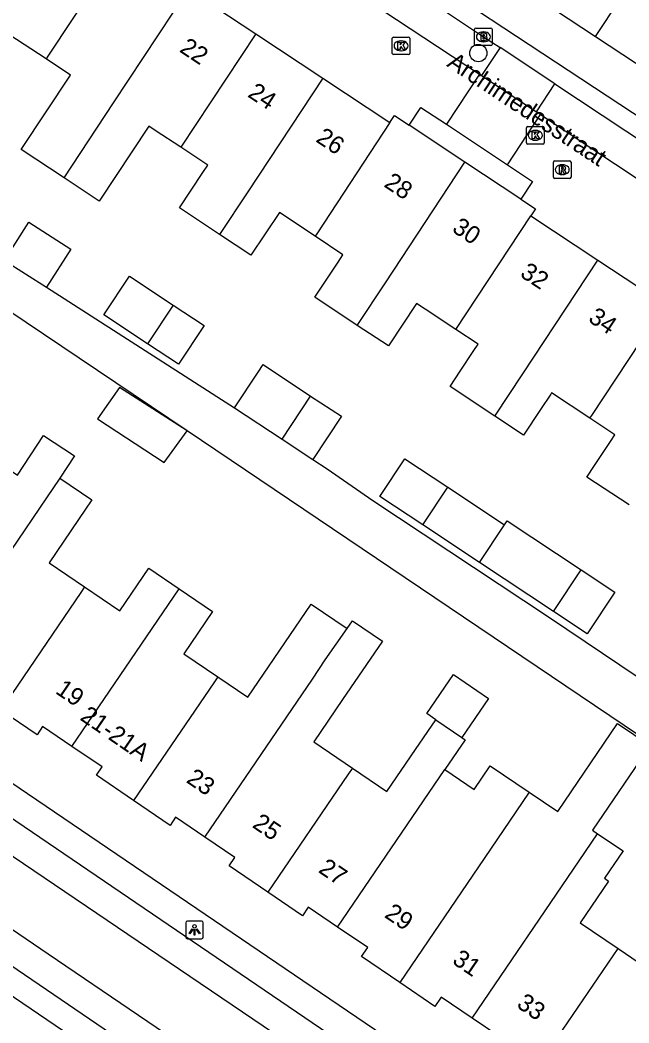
# Model space of a CAD drawing. Extents: x 159280 to 160375, y 384531 to 385872.
# Drawn here: x 159894.5 to 159929.1, y 384790.9 to 384847.8 of the extents above; entities that cross this region are included whole.
import ezdxf

# ---------------------------------------------------------------- set-up
doc = ezdxf.new("R2010")
doc.units = 0
for name, color, linetype in [('IMGEO_Boom', 7, 'Continuous'), ('IMGEO_Brandkraan', 7, 'Continuous'), ('IMGEO_Kolk', 7, 'Continuous'), ('IMGEO_Lichtpunt', 7, 'Continuous'), ('IMGEO_Openbare_ruimte_label', 7, 'Continuous'), ('IMGEO_Pand', 7, 'Continuous'), ('IMGEO_Pand_nummerreeks', 7, 'Continuous'), ('IMGEO_Rijbaan_lokaal_open', 7, 'Continuous'), ('IMGEO_Rioolput', 7, 'Continuous'), ('IMGEO_Voetpad_open', 7, 'Continuous')]:
    doc.layers.add(name, color=color, linetype=linetype)

msp = doc.modelspace()

# ---------------------------------------------------------------- linework, layer by layer
at = {"layer": 'IMGEO_Boom'}
msp.add_circle((159920.528, 384845.947), 0.489, dxfattribs=at)
at = {"layer": 'IMGEO_Brandkraan'}
for p, q in [((159920.315, 384846.443), (159920.315, 384847.295)), ((159920.39, 384847.369), (159921.242, 384847.369)), ((159920.803, 384847.149), (159920.828, 384847.149)), ((159921.316, 384847.295), (159921.316, 384846.443)), ((159920.826, 384846.589), (159920.801, 384846.589)), ((159921.242, 384846.369), (159920.39, 384846.369))]:
    msp.add_line(p, q, dxfattribs=at)
for points in [[(159920.315, 384846.443), (159920.315, 384847.295)], [(159920.39, 384847.369), (159921.242, 384847.369)], [(159920.663, 384847.069), (159920.663, 384846.669), (159920.876, 384846.669)], [(159920.894, 384847.069), (159920.663, 384847.069)], [(159920.842, 384846.988), (159920.788, 384846.988), (159920.788, 384846.912)], [(159921.316, 384847.295), (159921.316, 384846.443)], [(159920.788, 384846.912), (159920.841, 384846.912)], [(159920.85, 384846.836), (159920.788, 384846.836), (159920.788, 384846.755)], [(159920.788, 384846.755), (159920.85, 384846.755)], [(159921.242, 384846.369), (159920.39, 384846.369)]]:
    msp.add_lwpolyline(points, dxfattribs=at)
for centre, radius, start, end in [((159920.392, 384847.293), 0.0765, 91.552, 178.448), ((159920.392, 384847.293), 0.0765, 91.552, 178.448), ((159920.843, 384846.95), 0.0379, 267.8285, 90.9355), ((159920.898, 384846.924), 0.145, 59.4692, 91.5367), ((159920.923, 384846.971), 0.0922, 285.5137, 58.1501), ((159921.24, 384847.293), 0.0765, 1.552, 88.448), ((159921.24, 384847.293), 0.0765, 1.552, 88.448), ((159920.392, 384846.445), 0.0765, 181.552, 268.448), ((159920.392, 384846.445), 0.0765, 181.552, 268.448), ((159920.851, 384846.795), 0.0404, 269.8759, 90.5077), ((159920.882, 384846.92), 0.251, 268.6676, 293.5347), ((159920.928, 384846.779), 0.105, 301.3115, 78.989), ((159921.24, 384846.445), 0.0765, 271.552, 358.448), ((159921.24, 384846.445), 0.0765, 271.552, 358.448)]:
    msp.add_arc(centre, radius, start, end, dxfattribs=at)
for centre, major_axis, ratio, start_param, end_param in [((159920.802, 384846.869), (-0.387, 0.002), 0.722429, 4.712389, 7.853982), ((159920.827, 384846.869), (-0.39, 0.002), 0.717154, 1.570796, 4.712389)]:
    msp.add_ellipse(centre, major_axis=major_axis, ratio=ratio, start_param=start_param, end_param=end_param, dxfattribs=at)
at = {"layer": 'IMGEO_Kolk'}
for p, q in [((159915.647, 384845.933), (159915.647, 384846.785)), ((159915.722, 384846.859), (159916.574, 384846.859)), ((159916.135, 384846.639), (159916.16, 384846.639)), ((159916.648, 384846.785), (159916.648, 384845.933)), ((159916.574, 384845.859), (159915.722, 384845.859)), ((159916.158, 384846.079), (159916.133, 384846.079)), ((159923.261, 384840.854), (159923.261, 384841.706)), ((159923.336, 384841.78), (159924.188, 384841.78)), ((159923.749, 384841.56), (159923.774, 384841.56)), ((159924.262, 384841.706), (159924.262, 384840.854)), ((159924.188, 384840.78), (159923.336, 384840.78)), ((159923.772, 384841), (159923.747, 384841))]:
    msp.add_line(p, q, dxfattribs=at)
for points in [[(159915.647, 384845.933), (159915.647, 384846.785)], [(159915.722, 384846.859), (159916.574, 384846.859)], [(159915.968, 384846.559), (159916.091, 384846.559), (159916.091, 384846.408), (159916.221, 384846.559), (159916.385, 384846.559), (159916.239, 384846.408), (159916.392, 384846.159), (159916.24, 384846.159), (159916.155, 384846.323), (159916.091, 384846.256), (159916.091, 384846.159), (159915.968, 384846.159), (159915.968, 384846.559)], [(159916.648, 384846.785), (159916.648, 384845.933)], [(159916.574, 384845.859), (159915.722, 384845.859)], [(159923.261, 384840.854), (159923.261, 384841.706)], [(159923.336, 384841.78), (159924.188, 384841.78)], [(159923.582, 384841.48), (159923.705, 384841.48), (159923.705, 384841.329), (159923.835, 384841.48), (159923.999, 384841.48), (159923.853, 384841.329), (159924.006, 384841.08), (159923.854, 384841.08), (159923.769, 384841.244), (159923.705, 384841.177), (159923.705, 384841.08), (159923.582, 384841.08), (159923.582, 384841.48)], [(159924.262, 384841.706), (159924.262, 384840.854)], [(159924.188, 384840.78), (159923.336, 384840.78)]]:
    msp.add_lwpolyline(points, dxfattribs=at)
for centre, start, end in [((159915.724, 384846.783), 91.552, 178.448), ((159915.724, 384846.783), 91.552, 178.448), ((159916.572, 384846.783), 1.552, 88.448), ((159916.572, 384846.783), 1.552, 88.448), ((159915.724, 384845.935), 181.552, 268.448), ((159915.724, 384845.935), 181.552, 268.448), ((159916.572, 384845.935), 271.552, 358.448), ((159916.572, 384845.935), 271.552, 358.448), ((159923.338, 384841.704), 91.552, 178.448), ((159923.338, 384841.704), 91.552, 178.448), ((159924.186, 384841.704), 1.552, 88.448), ((159924.186, 384841.704), 1.552, 88.448), ((159923.338, 384840.856), 181.552, 268.448), ((159923.338, 384840.856), 181.552, 268.448), ((159924.186, 384840.856), 271.552, 358.448), ((159924.186, 384840.856), 271.552, 358.448)]:
    msp.add_arc(centre, 0.0765, start, end, dxfattribs=at)
for centre, major_axis, ratio, start_param, end_param in [((159916.134, 384846.359), (-0.387, 0.002), 0.722429, 4.712389, 7.853982), ((159916.159, 384846.359), (-0.39, 0.002), 0.717154, 1.570796, 4.712389), ((159923.748, 384841.28), (-0.387, 0.002), 0.722429, 4.712389, 7.853982), ((159923.773, 384841.28), (-0.39, 0.002), 0.717154, 1.570796, 4.712389)]:
    msp.add_ellipse(centre, major_axis=major_axis, ratio=ratio, start_param=start_param, end_param=end_param, dxfattribs=at)
at = {"layer": 'IMGEO_Lichtpunt'}
for p, q in [((159903.929, 384796.604), (159903.929, 384795.797)), ((159903.929, 384796.604), (159903.929, 384795.797)), ((159904.831, 384796.699), (159904.023, 384796.699)), ((159904.831, 384796.699), (159904.023, 384796.699)), ((159904.925, 384795.797), (159904.925, 384796.604)), ((159904.925, 384795.797), (159904.925, 384796.604)), ((159904.023, 384795.703), (159904.831, 384795.703)), ((159904.023, 384795.703), (159904.831, 384795.703))]:
    msp.add_line(p, q, dxfattribs=at)
for points in [[(159904.303, 384796.268), (159904.342, 384796.24), (159904.154, 384795.978), (159904.116, 384796.005), (159904.303, 384796.268)], [(159904.405, 384796.22), (159904.452, 384796.22), (159904.452, 384795.898), (159904.405, 384795.898), (159904.405, 384796.22)], [(159904.515, 384796.24), (159904.553, 384796.267), (159904.74, 384796.005), (159904.701, 384795.977), (159904.515, 384796.24)]]:
    msp.add_lwpolyline(points, dxfattribs=at)
msp.add_circle((159904.428, 384796.402), 0.0994, dxfattribs=at)
for centre, start, end in [((159904.023, 384796.604), 90, 180), ((159904.023, 384796.604), 90, 180), ((159904.831, 384796.604), 0, 90), ((159904.831, 384796.604), 0, 90), ((159904.023, 384795.797), 180, 270), ((159904.023, 384795.797), 180, 270), ((159904.831, 384795.797), 270, 0), ((159904.831, 384795.797), 270, 360)]:
    msp.add_arc(centre, 0.0946, start, end, dxfattribs=at)
at = {"layer": 'IMGEO_Pand'}
for points in [[(159927.177, 384846.897), (159929.93, 384851.064), (159932.923, 384855.595)], [(159900.283, 384852.086), (159896.11, 384845.763), (159896.007, 384845.613)], [(159922.587, 384849.929), (159927.177, 384846.897)], [(159897.031, 384838.868), (159899.84, 384843.124), (159904.091, 384849.565)], [(159904.091, 384849.565), (159907.899, 384847.043)], [(159896.007, 384845.613), (159893.903, 384847.006), (159892.349, 384844.66), (159890.652, 384845.784)], [(159907.899, 384847.043), (159903.648, 384840.603)], [(159907.899, 384847.043), (159911.707, 384844.521)], [(159927.177, 384846.897), (159931.767, 384843.864)], [(159897.031, 384838.868), (159894.593, 384840.482), (159897.395, 384844.694), (159896.007, 384845.613)], [(159911.707, 384844.521), (159907.459, 384838.085), (159905.851, 384835.649)], [(159911.707, 384844.521), (159915.513, 384842.001)], [(159915.513, 384842.001), (159911.357, 384835.7), (159911.263, 384835.56)], [(159915.513, 384842.001), (159915.777, 384842.399), (159916.595, 384841.858)], [(159903.648, 384840.603), (159902.203, 384841.56), (159901.842, 384841.799), (159899.026, 384837.547), (159897.031, 384838.868)], [(159919.769, 384839.756), (159916.595, 384841.858)], [(159905.851, 384835.649), (159903.573, 384837.162), (159904.899, 384839.167), (159905.182, 384839.592), (159903.648, 384840.603)], [(159913.658, 384830.497), (159915.255, 384832.916), (159919.769, 384839.756)], [(159922.937, 384837.658), (159919.769, 384839.756)], [(159922.937, 384837.658), (159923.762, 384837.112), (159923.497, 384836.712)], [(159911.263, 384835.56), (159909.243, 384836.898), (159907.624, 384834.475), (159905.851, 384835.649)], [(159893.651, 384834.187), (159895.036, 384836.353), (159897.421, 384834.828), (159896.036, 384832.662)], [(159919.246, 384830.273), (159923.497, 384836.712)], [(159923.497, 384836.712), (159927.31, 384834.199)], [(159913.658, 384830.497), (159911.258, 384832.104), (159912.575, 384834.093), (159912.85, 384834.509), (159911.263, 384835.56)], [(159893.651, 384834.187), (159896.036, 384832.662)], [(159921.465, 384825.342), (159923.055, 384827.751), (159927.31, 384834.199)], [(159927.31, 384834.199), (159931.124, 384831.685)], [(159901.764, 384829.455), (159899.286, 384831.091), (159900.733, 384833.283), (159903.211, 384831.647)], [(159903.211, 384831.647), (159904.972, 384830.484), (159903.526, 384828.293), (159901.764, 384829.455)], [(159903.211, 384831.647), (159901.764, 384829.455)], [(159919.246, 384830.273), (159917.508, 384831.424), (159917.021, 384831.747), (159915.429, 384829.343), (159913.658, 384830.497)], [(159926.861, 384825.23), (159926.972, 384825.394), (159931.124, 384831.685)], [(159921.465, 384825.342), (159918.925, 384827.025), (159919.5, 384827.893), (159920.278, 384829.068), (159920.518, 384829.431), (159919.246, 384830.273)], [(159906.697, 384825.818), (159908.032, 384827.844), (159908.315, 384828.273), (159911.014, 384826.492)], [(159904.008, 384824.524), (159900.178, 384826.983), (159898.927, 384825.201), (159902.705, 384822.725), (159904.008, 384824.524)], [(159926.861, 384825.23), (159924.679, 384826.676), (159924.631, 384826.604), (159924.053, 384825.73), (159923.086, 384824.269), (159921.465, 384825.342)], [(159909.396, 384824.039), (159911.014, 384826.492)], [(159911.014, 384826.492), (159912.758, 384825.342), (159911.14, 384822.889)], [(159906.697, 384825.818), (159909.396, 384824.039)], [(159929.088, 384820.31), (159926.679, 384821.889), (159927.119, 384822.553), (159928.021, 384823.915), (159928.273, 384824.295), (159926.861, 384825.23)], [(159892.175, 384823.123), (159892.343, 384823.374), (159894.387, 384822.007), (159895.864, 384824.258), (159897.628, 384823.101), (159896.794, 384821.831)], [(159909.396, 384824.039), (159911.14, 384822.889)], [(159917.387, 384819.177), (159914.945, 384820.795), (159916.36, 384822.932), (159918.799, 384821.316)], [(159896.794, 384821.831), (159896.035, 384820.715), (159889.939, 384811.756)], [(159896.794, 384821.831), (159898.605, 384820.601), (159897.846, 384819.483), (159896.183, 384817.035), (159898.193, 384815.669)], [(159917.387, 384819.177), (159918.799, 384821.316)], [(159918.799, 384821.316), (159922.011, 384819.189)], [(159920.595, 384817.052), (159917.387, 384819.177)], [(159920.595, 384817.052), (159922.011, 384819.189)], [(159922.011, 384819.189), (159922.157, 384819.41), (159926.36, 384816.626)], [(159924.795, 384814.271), (159920.595, 384817.052)], [(159898.193, 384815.669), (159900.198, 384814.306), (159901.837, 384816.717), (159903.548, 384815.554)], [(159926.36, 384816.626), (159928.267, 384815.362), (159926.706, 384813.005), (159924.795, 384814.271)], [(159924.795, 384814.271), (159926.36, 384816.626)], [(159898.193, 384815.669), (159897.979, 384815.354), (159893.434, 384808.676)], [(159897.464, 384806.614), (159903.548, 384815.554)], [(159903.548, 384815.554), (159905.445, 384814.264), (159903.817, 384811.868), (159905.747, 384810.557)], [(159905.747, 384810.557), (159907.451, 384809.398), (159911.041, 384814.68), (159913.079, 384813.295)], [(159913.079, 384813.295), (159913.39, 384813.742), (159915.083, 384812.59), (159912.827, 384809.272), (159911.199, 384806.878), (159913.39, 384805.388)], [(159905.008, 384801.466), (159911.113, 384810.437), (159911.848, 384811.527), (159913.079, 384813.295)], [(159918.11, 384808.125), (159917.602, 384808.471), (159919.11, 384810.688), (159921.097, 384809.337), (159919.589, 384807.119)], [(159905.747, 384810.557), (159905.514, 384810.225), (159900.968, 384803.545)], [(159897.464, 384806.614), (159895.813, 384807.736), (159895.498, 384807.273), (159893.434, 384808.676)], [(159913.39, 384805.388), (159915.344, 384804.06), (159916.963, 384806.441), (159918.11, 384808.125)], [(159918.11, 384808.125), (159919.589, 384807.119)], [(159923.414, 384804.015), (159925.029, 384802.918), (159928.425, 384807.915), (159930.276, 384806.657), (159927.013, 384801.855), (159927.295, 384801.663)], [(159900.968, 384803.545), (159898.862, 384804.977), (159899.182, 384805.446), (159897.464, 384806.614)], [(159919.589, 384807.119), (159919.778, 384806.991), (159918.632, 384805.306)], [(159918.632, 384805.306), (159920.296, 384804.175), (159921.207, 384805.515), (159923.414, 384804.015)], [(159913.39, 384805.388), (159913.148, 384805.031), (159908.595, 384798.339)], [(159912.547, 384796.365), (159918.632, 384805.306)], [(159923.414, 384804.015), (159920.861, 384800.263), (159916.066, 384793.217)], [(159905.008, 384801.466), (159903.352, 384802.591), (159903.043, 384802.135), (159900.968, 384803.545)], [(159920.174, 384791.199), (159926.24, 384800.113), (159927.295, 384801.663)], [(159927.295, 384801.663), (159928.737, 384800.683), (159927.683, 384799.132), (159927.919, 384798.972), (159926.311, 384796.606), (159928.451, 384795.152)], [(159908.595, 384798.339), (159906.391, 384799.836), (159906.712, 384800.308), (159905.008, 384801.466)], [(159912.547, 384796.365), (159910.883, 384797.496), (159910.552, 384797.009), (159908.595, 384798.339)], [(159916.066, 384793.217), (159913.902, 384794.687), (159914.254, 384795.204), (159912.547, 384796.365)], [(159928.451, 384795.152), (159930.42, 384793.813), (159932.062, 384796.228), (159933.625, 384795.166)], [(159923.641, 384788.084), (159928.451, 384795.152)], [(159920.174, 384791.199), (159918.428, 384792.386), (159918.068, 384791.856), (159916.066, 384793.217)], [(159923.641, 384788.084), (159921.397, 384789.609), (159921.75, 384790.128), (159920.174, 384791.199)]]:
    msp.add_lwpolyline(points, dxfattribs=at)
at = {"layer": 'IMGEO_Rijbaan_lokaal_open'}
for points in [[(159900.926, 384857.731), (159920.598, 384844.751)], [(159920.598, 384844.751), (159918.715, 384841.907)], [(159920.71, 384844.677), (159920.598, 384844.751)], [(159920.71, 384844.677), (159923.826, 384842.614)], [(159916.595, 384841.858), (159917.264, 384842.867), (159918.715, 384841.907)], [(159922.175, 384839.615), (159924.059, 384842.46)], [(159924.059, 384842.46), (159923.826, 384842.614)], [(159924.059, 384842.46), (159942.418, 384830.305)], [(159918.715, 384841.907), (159922.175, 384839.615)], [(159922.175, 384839.615), (159923.606, 384838.668), (159922.937, 384837.658)], [(159945.396, 384765.37), (159926.959, 384778.09), (159908.324, 384790.738), (159887.611, 384804.749)], [(159885.702, 384801.937), (159896.121, 384794.85), (159926.868, 384773.971), (159943.479, 384762.606)]]:
    msp.add_lwpolyline(points, dxfattribs=at)
at = {"layer": 'IMGEO_Rioolput'}
for p, q in [((159924.785, 384838.906), (159924.785, 384839.758)), ((159924.86, 384839.832), (159925.712, 384839.832)), ((159925.273, 384839.612), (159925.298, 384839.612)), ((159925.786, 384839.758), (159925.786, 384838.906)), ((159925.296, 384839.052), (159925.271, 384839.052)), ((159925.712, 384838.832), (159924.86, 384838.832))]:
    msp.add_line(p, q, dxfattribs=at)
for points in [[(159924.785, 384838.906), (159924.785, 384839.758)], [(159924.86, 384839.832), (159925.712, 384839.832)], [(159925.786, 384839.758), (159925.786, 384838.906)], [(159925.374, 384839.53), (159925.122, 384839.532), (159925.122, 384839.132)], [(159925.122, 384839.132), (159925.246, 384839.132), (159925.246, 384839.294), (159925.257, 384839.294)], [(159925.3, 384839.451), (159925.246, 384839.451), (159925.246, 384839.37)], [(159925.246, 384839.37), (159925.298, 384839.37)], [(159925.304, 384839.265), (159925.375, 384839.132), (159925.515, 384839.132), (159925.45, 384839.258)], [(159925.712, 384838.832), (159924.86, 384838.832)]]:
    msp.add_lwpolyline(points, dxfattribs=at)
for centre, radius, start, end in [((159924.862, 384839.756), 0.0765, 91.552, 178.448), ((159924.862, 384839.756), 0.0765, 91.552, 178.448), ((159925.71, 384839.756), 0.0765, 1.552, 88.448), ((159925.71, 384839.756), 0.0765, 1.552, 88.448), ((159925.256, 384839.241), 0.0533, 26.0293, 88.6989), ((159925.282, 384839.559), 0.19, 274.7715, 282.9687), ((159925.306, 384839.355), 0.0964, 77.0061, 93.1865), ((159925.32, 384839.412), 0.0378, 276.6634, 79.6772), ((159925.373, 384839.42), 0.109, 350.3612, 89.416), ((159925.371, 384839.42), 0.112, 277.5842, 350.9817), ((159925.355, 384839.205), 0.108, 29.5134, 73.7905), ((159924.862, 384838.908), 0.0765, 181.552, 268.448), ((159924.862, 384838.908), 0.0765, 181.552, 268.448), ((159925.71, 384838.908), 0.0765, 271.552, 358.448), ((159925.71, 384838.908), 0.0765, 271.552, 358.448)]:
    msp.add_arc(centre, radius, start, end, dxfattribs=at)
for centre, major_axis, ratio, start_param, end_param in [((159925.272, 384839.332), (-0.387, 0.002), 0.722429, 4.712389, 7.853982), ((159925.297, 384839.332), (-0.39, 0.002), 0.717154, 1.570796, 4.712389)]:
    msp.add_ellipse(centre, major_axis=major_axis, ratio=ratio, start_param=start_param, end_param=end_param, dxfattribs=at)
at = {"layer": 'IMGEO_Voetpad_open'}
for points in [[(159953.493, 384826.611), (159888.95, 384869.106), (159890.199, 384870.983)], [(159901.691, 384859.502), (159916.111, 384850.031), (159920.816, 384846.869), (159921.765, 384846.256)], [(159921.765, 384846.256), (159920.71, 384844.677)], [(159924.875, 384844.2), (159921.765, 384846.256)], [(159923.826, 384842.614), (159924.875, 384844.2)], [(159924.875, 384844.2), (159943.718, 384831.713), (159942.677, 384830.134)], [(159904.008, 384824.524), (159886.708, 384836.156)], [(159896.036, 384832.662), (159906.697, 384825.818)], [(159857.677, 384829.243), (159933.27, 384777.928)], [(159936.223, 384802.782), (159904.008, 384824.524)], [(159911.14, 384822.889), (159911.948, 384822.357), (159914.544, 384820.567), (159924.57, 384813.932), (159946.537, 384799.134), (159946.632, 384799.271)], [(159927.578, 384769.66), (159852.026, 384821.042)], [(159885.211, 384808.551), (159918.388, 384786.002)], [(159901.391, 384789.147), (159893.533, 384794.514)]]:
    msp.add_lwpolyline(points, dxfattribs=at)

# ---------------------------------------------------------------- texts
at = {"layer": 'IMGEO_Openbare_ruimte_label'}
msp.add_text('Archimedesstraat', height=1, rotation=326.5006, dxfattribs=at).set_placement((159918.689, 384845.229))
at = {"layer": 'IMGEO_Pand_nummerreeks'}
for s, rotation, p in [('22', 326.5736, (159903.525, 384846.055)), ('24', 326.5736, (159907.391, 384843.505)), ('26', 326.5736, (159911.254, 384840.955)), ('28', 326.5736, (159915.119, 384838.404)), ('30', 326.5736, (159918.981, 384835.854)), ('32', 326.5736, (159922.839, 384833.307)), ('34', 326.5736, (159926.705, 384830.757)), ('19', 325.759, (159896.482, 384809.663)), ('21-21A', 325.5939, (159897.88, 384808.156)), ('23', 325.76, (159903.904, 384804.611)), ('25', 325.76, (159907.652, 384802.06)), ('27', 325.76, (159911.401, 384799.508)), ('29', 325.76, (159915.149, 384796.957)), ('31', 325.76, (159918.991, 384794.341)), ('33', 325.76, (159922.646, 384791.854))]:
    msp.add_text(s, height=1, rotation=rotation, dxfattribs=at).set_placement(p)

doc.saveas('drawing.dxf')
